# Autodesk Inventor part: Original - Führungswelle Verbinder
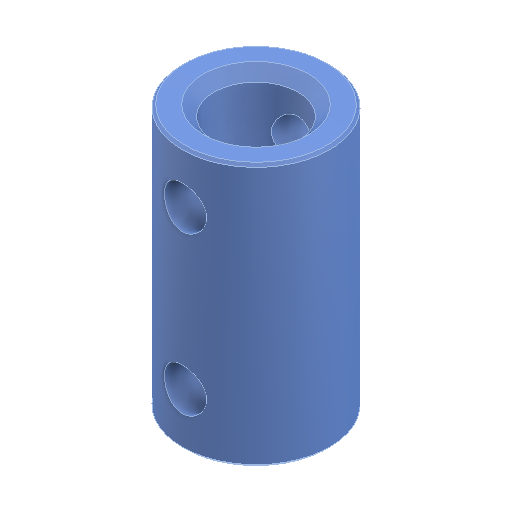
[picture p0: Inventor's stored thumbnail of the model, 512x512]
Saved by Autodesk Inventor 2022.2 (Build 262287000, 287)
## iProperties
Created: 2024-09
Part Number: Original - Führungswelle Verbinder
Material: Generico
Document SubType Name: Modeling
Designer: 18907419
Density: 1 g/cm^3
Appearance: Default
Author: 18907419
Revision Number: ANY
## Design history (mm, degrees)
feature "Schnitt-Linear austragen2"
node "Solido1"
